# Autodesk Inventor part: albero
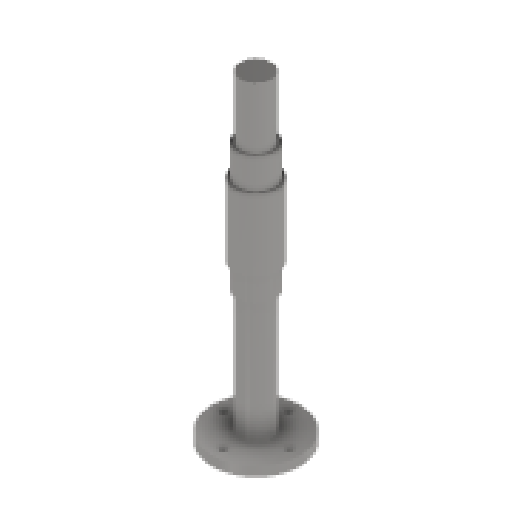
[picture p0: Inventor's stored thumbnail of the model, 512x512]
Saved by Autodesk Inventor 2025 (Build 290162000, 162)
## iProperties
Created: 2025-03
Part Number: albero
Material: Acciaio inossidabile
Document SubType Name: Modeling
Designer: R5800u
Density: 8 g/cm^3
Appearance: Semilucidato
Author: R5800u
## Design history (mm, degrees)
sketch "Schizzo1"
  geometry: C1 r 12.5 at (0, 0); 1 further point
  constraints: 1 centre point, 1 coincident
  dimensions: "d0" = 25 diameter of C1
extrude "Estrusione1" new body sketch "Schizzo1" distance "d1" = 100; taper "d2" = 0 deg
sketch "Schizzo2"
  geometry: C1 r 36 at (0, 0); 1 further point
  constraints: 1 centre point, 1 coincident
  dimensions: "d3" = 72 diameter of C1
extrude "Estrusione2" join sketch "Schizzo2" distance "d4" = 8; taper "d5" = 0 deg
sketch "Schizzo3"
  geometry: 2 further points
  dimensions: "d6" = 27 distance of point (0, 0) point (0, 27)
hole "Foro1" sketch "Schizzo3" at (0, 27) diameter "d7" = 6.4; stored, may be unused: countersink angle "d11" = 90 deg, drill point angle "d13" = 118 deg; dims "d8" = 6, "d9" = 12.6, "d10" = 2, "d12" = 8
pattern_circular "Serie circolare1" dims angle "d15" = 360 deg
sketch "Schizzo4"
  geometry: C1 r 15 at (0, 0); 1 further point
  constraints: 1 centre point, 1 coincident
  dimensions: "d17" = 30 diameter of C1
extrude "Estrusione3" join sketch "Schizzo4" distance "d18" = 20; taper "d19" = 0 deg
sketch "Schizzo5"
  geometry: C1 r 17.5 at (0, 0); 1 further point
  constraints: 1 centre point, 1 coincident
  dimensions: "d20" = 35 diameter of C1
extrude "Estrusione4" join sketch "Schizzo5" distance "d21" = 60; taper "d22" = 0 deg
sketch "Schizzo6"
  geometry: C1 r 15 at (0, 0); 1 further point
  constraints: 1 centre point, 1 coincident
  dimensions: "d23" = 30 diameter of C1
extrude "Estrusione5" join sketch "Schizzo6" distance "d24" = 25; taper "d25" = 0 deg
sketch "Schizzo7"
  geometry: C1 r 12.5 at (0, 0); 1 further point
  constraints: 1 centre point, 1 coincident
  dimensions: "d26" = 25 diameter of C1
extrude "Estrusione6" join sketch "Schizzo7" distance "d27" = 50; taper "d28" = 0 deg
node "Solido1"
